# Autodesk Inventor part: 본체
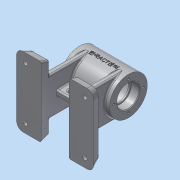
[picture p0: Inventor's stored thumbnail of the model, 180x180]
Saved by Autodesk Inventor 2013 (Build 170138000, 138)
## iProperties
Created: 2016-07
Part Number: 본체
Material: 알루미늄 6061
Document SubType Name: Modeling
Designer: dgall
Density: 2.71 g/cm^3
Mass: 498.152 g
Surface Area: 540.676 cm^2
Volume: 183.82 cm^3
Author: dgall
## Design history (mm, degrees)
sketch "스케치1"
  geometry: L1 (-35, 0)-(35, 0); L2 (35, 0)-(35, 27); L3 (35, 27)-(-35, 27); L4 (-35, 27)-(-35, 0); L5 (-35, 16)-(-23.3, 16); L6 (-23, 15.7)-(-23, 14); L7 (-23, 14)-(-21, 14); L8 (-21, 14)-(-21, 22); L9 (-21, 22)-(21, 22); L10 (21, 22)-(21, 14); L11 (21, 14)-(23, 14); L12 (23, 14)-(23, 15.7); L13 (23.3, 16)-(35, 16); A1 r 0.3 centre (-23.3, 15.7) between (-23, 15.7) and (-23.3, 16); A2 r 0.3 centre (23.3, 15.7) between (23.3, 16) and (23, 15.7); 4 further points
  constraints: 26 end point, 6 point on line, 5 parallel, 4 perpendicular, 4 point on circle, 4 tangent, 2 centre point, 2 collinear, 2 vertical, 1 coincident, 1 equal radius, 1 horizontal, 1 midpoint
  dimensions: "d0" = 12 distance of L5.start point (-23, 16); "d2" = 42 distance of L8.end L9.end; "d3" = 12 distance of point (23, 16) L13.end; "d4" = 70 distance of L1.start L1.end; "d5" = 54 diameter of L3 L1; "d6" = 32 diameter of L5 L1; "d7" = 28 diameter of L7 L1; "d8" = 44 diameter of L9 L1; "d9" = 28 diameter of L11 L1; "d10" = 32 diameter of L13 L1; "d12" = 0.3 radius of A1
revolve "회전1" sketch "스케치1" stored, may be unused: angle "d11" = 90 deg
node "작업 평면1"
sketch "스케치2"
  geometry: L1 (-55, 50)-(-20, 50); L2 (-20, 50)-(-20, -50); L3 (-20, -50)-(-55, -50); L4 (-55, -50)-(-55, 50); 2 further points
  constraints: 8 end point, 2 parallel, 1 horizontal, 1 horizontal alignment, 1 midpoint, 1 perpendicular
  dimensions: "d14" = 35 distance between parallel lines of L2 L4; "d16" = 100 distance between parallel lines of L3 L1; "d17" = 55 distance from line of L4 point (0, 0)
extrude "돌출1" join sketch "스케치2" distance "d18" = 12; taper "d19" = 0 deg
sketch "스케치3"
  geometry: L1 (20, 50)-(20, -50) reference; L2 (20, 27)-(28, 27); L3 (28, 27)-(28, -27); L4 (28, -27)-(20, -27); L5 (20, -27)-(20, 27); 2 further points
  constraints: 8 end point, 2 parallel, 1 horizontal, 1 horizontal alignment, 1 midpoint, 1 perpendicular, 1 point on line
  dimensions: "d21" = 8 distance of L3.end L4.end; "d23" = 54 distance between parallel lines of L4 L2
extrude "돌출2" join sketch "스케치3" stored distance "d24" = 12; taper "d25" = 0 deg
fillet "모깎기9" dims "d111" = 10
feature "면 기울기2" dims angle "d26" = 20 deg
feature "면 기울기3" dims angle "d27" = 20 deg
sketch "스케치4"
  geometry: L1 (55, 40.603)-(55, -40.603) reference; 10 further points; 1 other entity
  constraints: 1 other
  dimensions: "d29" = 12.5 dimension on point (42.5, -37.5); "d30" = 12.5 distance from line of point (42.5, -37.5) L1
hole "구멍1" sketch "스케치4" at (42.5, -37.5) diameter "d31" = 6; stored, may be unused: countersink angle "d35" = 90 deg, drill point angle "d37" = 118 deg; dims "d32" = 6, "d33" = 10, "d34" = 4, "d36" = 8
sketch "스케치12"
  geometry: C1 r 16 at (0, 0) reference; 1 further point
  constraints: 1 vertical alignment
  dimensions: "d81" = 21 distance of C1.centre point (0, 21)
hole "구멍4" sketch "스케치12" at (0, 21) diameter "d82" = 3.242; stored, may be unused: countersink angle "d86" = 90 deg, drill point angle "d88" = 118 deg; dims "d83" = 8, "d84" = 10, "d85" = 4, "d87" = 10
sketch "스케치5"
  geometry: L1 (-19.942, -48)-(20.009, -48); L2 (-35, -27)-(35, -27) reference; 1 further point
  constraints: 2 end point, 1 horizontal
  dimensions: "d38" = 21 distance between parallel lines of L1 L2
feature "리브1" sketch "스케치5" dims "d39" = 1, "d40" = 8, "d41" = 0, "d42" = 0, "d43" = 1, "d44" = 1
sketch "스케치6"
  geometry: L1 (40, -21.298)-(0, -21.298) reference; L2 (12, -7.798)-(28, -7.798); L3 (28, -14.798)-(12, -14.798); L4 (20, -7.798)-(20, -14.976); L5 (65.603, -43.298)-(40, -43.298) reference; A1 r 3.5 centre (28, -11.298) between (28, -14.798) and (28, -7.798); A2 r 3.5 centre (12, -11.298) between (12, -7.798) and (12, -14.798); 3 further points
  constraints: 6 end point, 4 point on circle, 2 centre point, 2 parallel, 2 tangent, 1 equal radius, 1 midpoint, 1 perpendicular, 1 vertical alignment
  dimensions: "d45" = 3.5 radius of A1; "d47" = 23 dimension on A1 A2; "d49" = 11.5 dimension on A2 L4; "d50" = 32 distance from line of L5 A1.centre
extrude "돌출3" cut sketch "스케치6" stored distance "d51" = 12; taper "d52" = 0 deg
sketch "스케치7"
  geometry: L1 (0, 0)-(-12.358, 0); L2 (0, 0)-(-25.441, -15.898)
  constraints: 4 end point, 1 horizontal
  dimensions: "d53" = 30 distance of L1.start L2.end; "d55" = 32 deg angle of L2 L1
node "작업 평면2"
sketch "스케치8"
  geometry: C1 r 6 at (0, 0); 1 further point
  constraints: 1 centre point, 1 coincident
  dimensions: "d56" = 12 diameter of C1
extrude "돌출4" join sketch "스케치8" stored distance "d58" = 12; taper "d59" = 0 deg
sketch "스케치9"
  geometry: 1 further point
hole "구멍2" sketch "스케치9" at (0, 0) diameter "d60" = 5.188; stored, may be unused: countersink angle "d64" = 90 deg, drill point angle "d66" = 118 deg; dims "d61" = 6, "d62" = 10, "d63" = 4, "d65" = 13
node "작업 평면3"
sketch "스케치11"
  geometry: L1 (-35, 27)-(-35, -27) reference; L2 (35, 27)-(35, -27) reference; C1 r 5 at (13, 0); 1 further point
  constraints: 1 centre point, 1 horizontal alignment
  dimensions: "d69" = 10 diameter of C1; "d97" = 22 distance from line of L2 C1.centre
extrude "돌출5" join sketch "스케치11" stored distance "d70" = 12; taper "d71" = 0 deg
hole "구멍3" diameter "d74" = 5.188; stored, may be unused: countersink angle "d78" = 90 deg, drill point angle "d80" = 118 deg; dims "d72" = 10, "d73" = 10, "d75" = 6, "d76" = 10, "d77" = 4, "d79" = 18
node "작업 평면4"
sketch "스케치13"
  geometry: L1 (-35, -27)-(-35, 27) reference; L2 (-35, 27)-(35, 27) reference; 2 further points
  constraints: 1 other
  dimensions: "d93" = 35 distance from line of point (0, 0) L1; "d94" = 27 distance from line of point (0, 0) L2
feature "엠보싱1" sketch "스케치13" dims "d0" = 12, "d2" = 42, "d3" = 12, "d4" = 70, "d5" = 54, "d6" = 32, "d7" = 28, "d8" = 44, "d9" = 28, "d10" = 32, "d12" = 0.3, "d95" = 0.5, "d96" = 0
fillet "모깎기2" dims "d98" = 2
fillet "모깎기3" dims "d99" = 2
fillet "모깎기4" dims "d100" = 2
fillet "모깎기5" dims "d101" = 2
chamfer "모따기1" distance "d102" = 1; stored, may be unused: second distance "d103" = 2, angle "d104" = 45 deg
chamfer "모따기2" distance "d105" = 1; stored, may be unused: second distance "d106" = 2, angle "d107" = 45 deg
fillet "모깎기6" dims "d108" = 2
fillet "모깎기7" dims "d109" = 2
node "솔리드1"
mirror "대칭1"
pattern_circular "원형 패턴1" dims angle "d90" = 360 deg
mirror "대칭2"
other parameters: "d92" = 43
